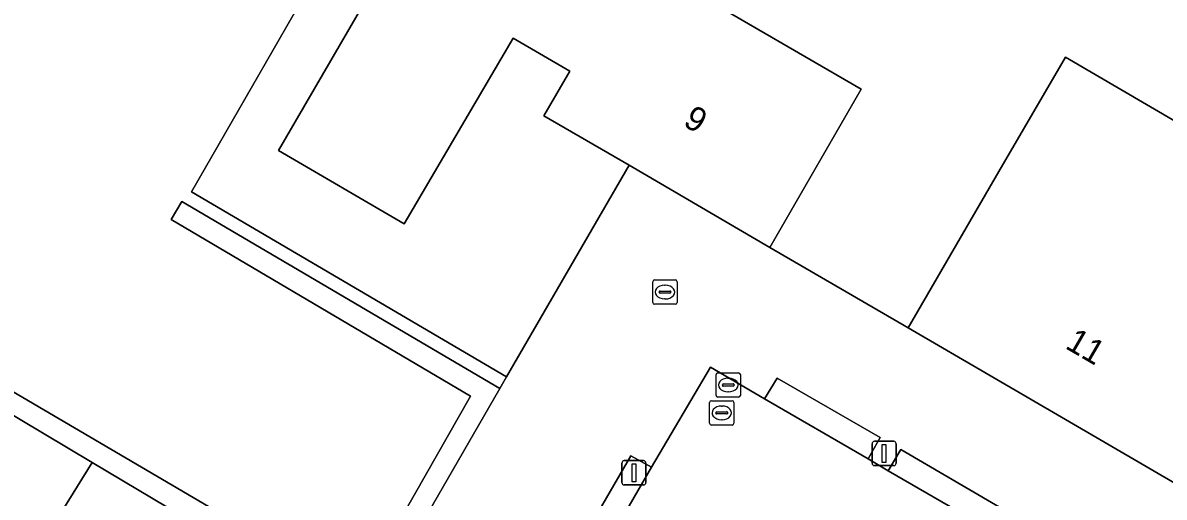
# Model space of a CAD drawing. Extents: x 156502 to 159075, y 384229 to 386100.
# Drawn here: x 157106.1 to 157152.94, y 385899.66 to 385919.13 of the extents above; entities that cross this region are included whole.
import ezdxf

# ---------------------------------------------------------------- set-up
doc = ezdxf.new("R2010")
doc.units = 0
for name, color, linetype in [('IMGEO_Berm_groen', 7, 'Continuous'), ('IMGEO_Erf', 7, 'Continuous'), ('IMGEO_Groenvoorziening', 7, 'Continuous'), ('IMGEO_Haag', 7, 'Continuous'), ('IMGEO_Hek', 7, 'Continuous'), ('IMGEO_Kolk', 7, 'Continuous'), ('IMGEO_Lichtmast', 7, 'Continuous'), ('IMGEO_Pand', 7, 'Continuous'), ('IMGEO_Pand_nummerreeks', 7, 'Continuous'), ('IMGEO_Parkeervlak_open', 7, 'Continuous'), ('IMGEO_Rijbaan_lokaal_open', 7, 'Continuous'), ('IMGEO_Rioolput', 7, 'Continuous'), ('IMGEO_Voetpad_open', 7, 'Continuous')]:
    doc.layers.add(name, color=color, linetype=linetype)

msp = doc.modelspace()

# ---------------------------------------------------------------- linework, layer by layer
at = {"layer": 'IMGEO_Berm_groen'}
msp.add_lwpolyline([(157108.945, 385901.089), (157104.008, 385904.025), (157101.482, 385899.753), (157106.365, 385896.913)], close=True, dxfattribs=at)
at = {"layer": 'IMGEO_Erf'}
for points in [[(157118.024, 385920.915), (157113.026, 385912.196), (157125.953, 385904.606), (157130.978, 385913.286), (157127.481, 385915.322), (157128.55, 385917.146), (157126.22, 385918.509), (157121.756, 385910.877), (157116.588, 385913.898), (157123.721, 385926.173)], [(157131.249, 385921.791), (157140.507, 385916.414), (157136.759, 385909.918), (157142.433, 385906.61), (157146.148, 385913.037), (157148.886, 385917.721), (157160.243, 385911.082)]]:
    msp.add_lwpolyline(points, dxfattribs=at)
at = {"layer": 'IMGEO_Groenvoorziening'}
for points in [[(157112.186, 385911.057), (157112.621, 385911.796), (157125.678, 385904.13), (157125.953, 385904.606), (157113.026, 385912.196), (157118.024, 385920.915), (157107.2, 385927.397), (157106.467, 385927.872), (157094.868, 385912.695), (157093.201, 385911.323), (157119.849, 385895.683), (157124.471, 385903.814)], [(157093.201, 385911.323), (157092.797, 385910.633), (157097.842, 385907.574), (157104.008, 385904.025), (157108.945, 385901.089), (157115.174, 385897.385), (157120.156, 385894.568), (157120.993, 385896.017), (157125.678, 385904.13), (157112.621, 385911.796), (157112.186, 385911.057), (157124.471, 385903.814), (157119.849, 385895.683)], [(157140.788, 385901.231), (157141.277, 385902.115), (157137.049, 385904.554), (157136.535, 385903.695)], [(157126.435, 385891.435), (157131.896, 385900.891), (157131.057, 385901.357), (157125.606, 385891.963)], [(157151.032, 385895.3), (157151.51, 385896.134), (157142.124, 385901.615), (157141.609, 385900.746)]]:
    msp.add_lwpolyline(points, close=True, dxfattribs=at)
at = {"layer": 'IMGEO_Haag'}
for points in [[(157097.842, 385907.574), (157104.008, 385904.025), (157108.945, 385901.089), (157115.174, 385897.385), (157120.156, 385894.568), (157120.993, 385896.017), (157125.678, 385904.13), (157112.621, 385911.796), (157112.186, 385911.057), (157124.471, 385903.814), (157119.849, 385895.683), (157093.201, 385911.323), (157092.797, 385910.633)], [(157140.788, 385901.231), (157141.277, 385902.115), (157137.049, 385904.554), (157136.535, 385903.695)], [(157126.435, 385891.435), (157131.896, 385900.891), (157131.057, 385901.357), (157125.606, 385891.963)], [(157151.032, 385895.3), (157151.51, 385896.134), (157142.124, 385901.615), (157141.609, 385900.746)]]:
    msp.add_lwpolyline(points, close=True, dxfattribs=at)
at = {"layer": 'IMGEO_Hek'}
for points in [[(157125.953, 385904.606), (157113.026, 385912.196), (157118.024, 385920.915)], [(157125.953, 385904.606), (157130.978, 385913.286)], [(157136.759, 385909.918), (157142.433, 385906.61)]]:
    msp.add_lwpolyline(points, dxfattribs=at)
at = {"layer": 'IMGEO_Kolk'}
for p, q in [((157134.547, 385903.841), (157134.547, 385904.693)), ((157134.622, 385904.767), (157135.474, 385904.767)), ((157135.035, 385904.547), (157135.06, 385904.547)), ((157135.548, 385904.693), (157135.548, 385903.841)), ((157134.806, 385904.261), (157134.806, 385904.273)), ((157135.244, 385904.224), (157134.846, 385904.224)), ((157134.849, 385904.31), (157135.247, 385904.31)), ((157135.29, 385904.273), (157135.29, 385904.261)), ((157135.474, 385903.767), (157134.622, 385903.767)), ((157135.058, 385903.987), (157135.033, 385903.987))]:
    msp.add_line(p, q, dxfattribs=at)
for points in [[(157134.547, 385903.841), (157134.547, 385904.693)], [(157134.622, 385904.767), (157135.474, 385904.767)], [(157135.548, 385904.693), (157135.548, 385903.841)], [(157135.474, 385903.767), (157134.622, 385903.767)]]:
    msp.add_lwpolyline(points, dxfattribs=at)
for centre, radius, start, end in [((157134.624, 385904.691), 0.0765, 91.552, 178.448), ((157134.624, 385904.691), 0.0765, 91.552, 178.448), ((157135.472, 385904.691), 0.0765, 1.552, 88.448), ((157135.472, 385904.691), 0.0765, 1.552, 88.448), ((157134.846, 385904.27), 0.0403, 85.8775, 175.7526), ((157134.843, 385904.26), 0.0366, 178.938, 274.7102), ((157135.247, 385904.267), 0.043, 264.8664, 352.4533), ((157135.251, 385904.272), 0.0386, 1.7309, 96.639), ((157134.624, 385903.843), 0.0765, 181.552, 268.448), ((157134.624, 385903.843), 0.0765, 181.552, 268.448), ((157135.472, 385903.843), 0.0765, 271.552, 358.448), ((157135.472, 385903.843), 0.0765, 271.552, 358.448)]:
    msp.add_arc(centre, radius, start, end, dxfattribs=at)
for centre, major_axis, ratio, start_param, end_param in [((157135.034, 385904.267), (-0.387, 0.002), 0.722429, 4.712389, 7.853982), ((157135.059, 385904.267), (-0.39, 0.002), 0.717154, 1.570796, 4.712389)]:
    msp.add_ellipse(centre, major_axis=major_axis, ratio=ratio, start_param=start_param, end_param=end_param, dxfattribs=at)
at = {"layer": 'IMGEO_Lichtmast'}
for p, q in [((157140.949, 385901.057), (157140.949, 385901.857)), ((157140.949, 385901.857), (157140.949, 385901.057)), ((157141.049, 385901.957), (157141.839, 385901.957)), ((157141.839, 385901.957), (157141.049, 385901.957)), ((157141.939, 385901.857), (157141.939, 385901.057)), ((157141.939, 385901.057), (157141.939, 385901.857)), ((157130.682, 385900.263), (157130.682, 385901.063)), ((157130.682, 385901.063), (157130.682, 385900.263)), ((157130.782, 385901.163), (157131.572, 385901.163)), ((157131.572, 385901.163), (157130.782, 385901.163)), ((157131.672, 385901.063), (157131.672, 385900.263)), ((157131.672, 385900.263), (157131.672, 385901.063)), ((157141.839, 385900.957), (157141.049, 385900.957)), ((157141.049, 385900.957), (157141.839, 385900.957)), ((157131.572, 385900.163), (157130.782, 385900.163)), ((157130.782, 385900.163), (157131.572, 385900.163))]:
    msp.add_line(p, q, dxfattribs=at)
for points in [[(157141.369, 385901.832), (157141.519, 385901.832), (157141.519, 385901.082), (157141.369, 385901.082), (157141.369, 385901.832)], [(157131.102, 385901.038), (157131.252, 385901.038), (157131.252, 385900.288), (157131.102, 385900.288), (157131.102, 385901.038)]]:
    msp.add_lwpolyline(points, dxfattribs=at)
for centre, start, end in [((157141.049, 385901.857), 90, 180), ((157141.049, 385901.857), 90, 180), ((157141.839, 385901.857), 0, 90), ((157141.839, 385901.857), 360, 90), ((157130.782, 385901.063), 90, 180), ((157130.782, 385901.063), 90, 180), ((157131.572, 385901.063), 0, 90), ((157131.572, 385901.063), 360, 90), ((157141.049, 385901.057), 180, 270), ((157141.049, 385901.057), 180, 270), ((157141.839, 385901.057), 270, 0), ((157141.839, 385901.057), 270, 0), ((157130.782, 385900.263), 180, 270), ((157130.782, 385900.263), 180, 270), ((157131.572, 385900.263), 270, 0), ((157131.572, 385900.263), 270, 0)]:
    msp.add_arc(centre, 0.1, start, end, dxfattribs=at)
at = {"layer": 'IMGEO_Pand'}
for points in [[(157136.759, 385909.918), (157140.507, 385916.414), (157131.249, 385921.791), (157130.991, 385921.317), (157128.64, 385922.686), (157128.916, 385923.151), (157123.721, 385926.173), (157116.588, 385913.898), (157121.756, 385910.877), (157126.22, 385918.509), (157128.55, 385917.146), (157127.481, 385915.322), (157130.978, 385913.286)], [(157159, 385908.955), (157160.243, 385911.082), (157148.886, 385917.721), (157146.148, 385913.037), (157142.433, 385906.61), (157153.769, 385900.007)]]:
    msp.add_lwpolyline(points, close=True, dxfattribs=at)
at = {"layer": 'IMGEO_Parkeervlak_open'}
msp.add_lwpolyline([(157112.736, 385893.192), (157115.174, 385897.385), (157108.945, 385901.089), (157106.365, 385896.913)], close=True, dxfattribs=at)
at = {"layer": 'IMGEO_Rijbaan_lokaal_open'}
msp.add_lwpolyline([(157172.275, 385882.9), (157162.851, 385888.415), (157162.018, 385888.901), (157157.792, 385891.329), (157151.032, 385895.3), (157141.609, 385900.746), (157140.788, 385901.231), (157136.535, 385903.695), (157134.317, 385905), (157131.896, 385900.891), (157126.435, 385891.435), (157125.704, 385890.195), (157117.969, 385876.968), (157117.795, 385876.679), (157112.461, 385867.56), (157109.666, 385862.678)], dxfattribs=at)
at = {"layer": 'IMGEO_Rioolput'}
for p, q in [((157131.95, 385907.655), (157131.95, 385908.507)), ((157132.025, 385908.581), (157132.877, 385908.581)), ((157132.438, 385908.361), (157132.463, 385908.361)), ((157132.951, 385908.507), (157132.951, 385907.655)), ((157132.209, 385908.075), (157132.209, 385908.087)), ((157132.647, 385908.038), (157132.249, 385908.038)), ((157132.252, 385908.124), (157132.65, 385908.124)), ((157132.461, 385907.801), (157132.436, 385907.801)), ((157132.693, 385908.087), (157132.693, 385908.075)), ((157132.877, 385907.581), (157132.025, 385907.581)), ((157134.357, 385903.624), (157135.209, 385903.624)), ((157134.282, 385902.698), (157134.282, 385903.55)), ((157134.541, 385903.118), (157134.541, 385903.13)), ((157134.584, 385903.167), (157134.982, 385903.167)), ((157134.77, 385903.404), (157134.795, 385903.404)), ((157135.025, 385903.13), (157135.025, 385903.118)), ((157135.283, 385903.55), (157135.283, 385902.698)), ((157135.209, 385902.624), (157134.357, 385902.624)), ((157134.979, 385903.081), (157134.581, 385903.081)), ((157134.793, 385902.844), (157134.768, 385902.844))]:
    msp.add_line(p, q, dxfattribs=at)
for points in [[(157131.95, 385907.655), (157131.95, 385908.507)], [(157132.025, 385908.581), (157132.877, 385908.581)], [(157132.951, 385908.507), (157132.951, 385907.655)], [(157132.877, 385907.581), (157132.025, 385907.581)], [(157134.357, 385903.624), (157135.209, 385903.624)], [(157134.282, 385902.698), (157134.282, 385903.55)], [(157135.283, 385903.55), (157135.283, 385902.698)], [(157135.209, 385902.624), (157134.357, 385902.624)]]:
    msp.add_lwpolyline(points, dxfattribs=at)
for centre, radius, start, end in [((157132.027, 385908.505), 0.0765, 91.552, 178.448), ((157132.027, 385908.505), 0.0765, 91.552, 178.448), ((157132.875, 385908.505), 0.0765, 1.552, 88.448), ((157132.875, 385908.505), 0.0765, 1.552, 88.448), ((157132.249, 385908.084), 0.0403, 85.8775, 175.7526), ((157132.246, 385908.074), 0.0366, 178.938, 274.7102), ((157132.65, 385908.081), 0.043, 264.8664, 352.4533), ((157132.654, 385908.086), 0.0386, 1.7309, 96.639), ((157132.027, 385907.657), 0.0765, 181.552, 268.448), ((157132.027, 385907.657), 0.0765, 181.552, 268.448), ((157132.875, 385907.657), 0.0765, 271.552, 358.448), ((157132.875, 385907.657), 0.0765, 271.552, 358.448), ((157134.359, 385903.548), 0.0765, 91.552, 178.448), ((157134.359, 385903.548), 0.0765, 91.552, 178.448), ((157135.207, 385903.548), 0.0765, 1.552, 88.448), ((157135.207, 385903.548), 0.0765, 1.552, 88.448), ((157134.581, 385903.127), 0.0403, 85.8775, 175.7526), ((157134.578, 385903.117), 0.0366, 178.938, 274.7102), ((157134.982, 385903.124), 0.043, 264.8664, 352.4533), ((157134.986, 385903.129), 0.0386, 1.7309, 96.639), ((157134.359, 385902.7), 0.0765, 181.552, 268.448), ((157134.359, 385902.7), 0.0765, 181.552, 268.448), ((157135.207, 385902.7), 0.0765, 271.552, 358.448), ((157135.207, 385902.7), 0.0765, 271.552, 358.448)]:
    msp.add_arc(centre, radius, start, end, dxfattribs=at)
for centre, major_axis, ratio, start_param, end_param in [((157132.437, 385908.081), (-0.387, 0.002), 0.722429, 4.712389, 7.853982), ((157132.462, 385908.081), (-0.39, 0.002), 0.717154, 1.570796, 4.712389), ((157134.769, 385903.124), (-0.387, 0.002), 0.722429, 4.712389, 7.853982), ((157134.794, 385903.124), (-0.39, 0.002), 0.717154, 1.570796, 4.712389)]:
    msp.add_ellipse(centre, major_axis=major_axis, ratio=ratio, start_param=start_param, end_param=end_param, dxfattribs=at)
at = {"layer": 'IMGEO_Voetpad_open'}
for points in [[(157226.078, 385857.975), (157218.954, 385862.085), (157207.627, 385868.664), (157195.952, 385875.233), (157185.093, 385881.809), (157167.911, 385891.794), (157163.686, 385894.272), (157153.769, 385900.007), (157142.433, 385906.61), (157136.759, 385909.918), (157130.978, 385913.286), (157125.953, 385904.606), (157125.678, 385904.13), (157120.993, 385896.017), (157120.156, 385894.568), (157117.68, 385890.28), (157119.669, 385889.108)], [(157125.704, 385890.195), (157126.435, 385891.435), (157125.606, 385891.963), (157131.057, 385901.357), (157131.896, 385900.891), (157134.317, 385905), (157136.535, 385903.695), (157137.049, 385904.554), (157141.277, 385902.115), (157140.788, 385901.231), (157141.609, 385900.746), (157142.124, 385901.615), (157151.51, 385896.134), (157151.032, 385895.3), (157157.792, 385891.329)]]:
    msp.add_lwpolyline(points, dxfattribs=at)

# ---------------------------------------------------------------- texts
at = {"layer": 'IMGEO_Pand_nummerreeks'}
for s, rotation, p in [('9', 329.778, (157133.151, 385914.936)), ('11', 329.7765, (157148.832, 385905.799))]:
    msp.add_text(s, height=1, rotation=rotation, dxfattribs=at).set_placement(p)

doc.saveas('drawing.dxf')
